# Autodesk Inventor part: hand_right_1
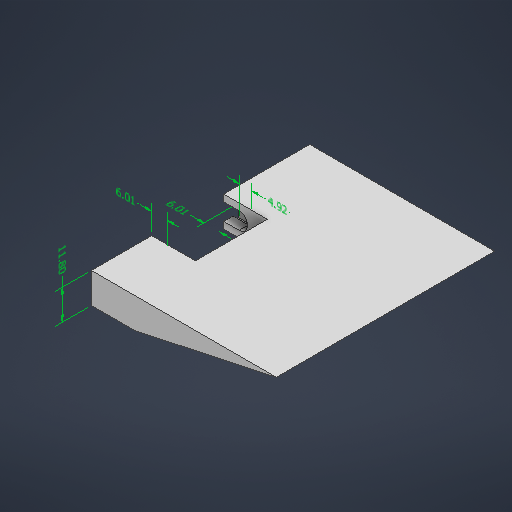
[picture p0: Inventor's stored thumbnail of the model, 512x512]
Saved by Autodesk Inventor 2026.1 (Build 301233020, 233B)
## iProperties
Created: 2025-10
Part Number: hand_right_1
Material: Generic
Document SubType Name: Modeling
Designer: Asus
Density: 1 g/cm^3
Appearance: Default
Author: Asus
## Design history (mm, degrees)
node "Annotations"
  node "Linear Dimension 2" dims "d2" = 28, "d19" = 6.01 (derived), "d25" = 8.5, "d26" = 60, "d27" = 12.02, "d28" = 72.02 (derived)
  node "Linear Dimension 3" dims "d2" = 28, "d20" = 6.01 (derived), "d25" = 8.5, "d26" = 60, "d27" = 12.02, "d28" = 72.02 (derived)
  node "Linear Dimension 4" dims "d2" = 28, "d23" = 4.915 (derived), "d25" = 8.5, "d26" = 60, "d27" = 12.02, "d28" = 72.02 (derived)
  node "Linear Dimension 5" dims "d2" = 28, "d25" = 8.5, "d26" = 60, "d27" = 12.02, "d28" = 72.02 (derived), "d31" = 11.8 (derived)
sketch "Sketch1"
  geometry: L1 (0, 0)-(60, 0); L2 (55.02, -23.5)-(55.02, -51.5); L3 (60, -75)-(0, -75); L4 (0, -75)-(0, 0); L5 (55.02, -23.5)-(72.02, -23.5); L6 (72.02, -23.5)-(72.02, -51.5); L7 (72.02, -51.5)-(55.02, -51.5); L8 (55.02, -51.5)-(55.02, -23.5); L9 (72.02, -51.5)-(55.02, -51.5); L10 (60, -75)-(72.02, -75); L11 (72.02, -75)-(72.02, -51.5); L12 (72.02, -23.5)-(55.02, -23.5); L13 (60, 0)-(72.02, 0); L14 (72.02, 0)-(72.02, -23.5); 3 further points
  constraints: 28 end point, 6 parallel, 4 horizontal, 4 midpoint, 2 perpendicular
  dimensions: "d2" = 28 distance of L5.end L6.end; "d25" = 8.5 distance of L2.end point (63.52, -51.5); "d26" = 60 distance of L3.start L3.end; "d27" = 12.02 distance of L3.start L10.end; "d28" = 72.02 distance between parallel lines of L4 L11 (derived)
extrude "Extrusion1" new body sketch "Sketch1" distance "d4" = 11.8; taper "d5" = 0 deg
sketch "Sketch2"
  geometry: L1 (17, 0)-(17, 11.8) reference; C1 r 2 at (10.99, 5.9); 1 further point
  constraints: 1 centre point
  dimensions: "d6" = 4 diameter of C1; "d7" = 6.01 distance from line of L1 C1.centre
extrude "Extrusion2" cut sketch "Sketch2" distance "d8" = 2; taper "d9" = 0 deg
sketch "Sketch3"
  geometry: L1 (6.01, 9.189)-(0, 9.189); L2 (0, 0)-(0, 11.8) reference; L3 (6.01, 2.589)-(0, 2.589); A1 r 3.3 centre (6.01, 5.889) between (6.01, 2.589) and (6.01, 9.189); 1 further point
  constraints: 4 end point, 2 point on circle, 2 point on line, 1 centre point, 1 horizontal, 1 parallel, 1 tangent
  dimensions: "d10" = 6.6 diameter of A1; "d21" = 6.01 distance from line of L2 A1.centre; "d22" = 6.01 distance of L1.start L1.end
extrude "Extrusion3" cut sketch "Sketch3" distance "d11" = 3.65; taper "d12" = 0 deg
sketch "Sketch4"
  geometry: L1 (19.85, 10.764)-(17.75, 10.764); L2 (17.75, 10.764)-(17.75, 1.014); L3 (17.75, 1.014)-(19.85, 1.014); L4 (19.85, 1.014)-(19.85, 10.764); L5 (19.85, 2.589)-(19.85, 9.189) reference; 2 further points
  constraints: 8 end point, 2 midpoint, 2 parallel, 1 horizontal, 1 perpendicular
  dimensions: "d13" = 2.1 distance of L3.end L2.end; "d14" = 9.75 distance of L1.end L2.end
extrude "Extrusion4" cut sketch "Sketch4" distance "d15" = 10.925; taper "d16" = 0 deg
sketch "Sketch5"
  geometry: L1 (17, 0)-(17, 11.8) reference; L2 (72.02, 11.8)-(0, 11.8) reference; L3 (17, 0)-(72.02, 11.8); L4 (72.02, 11.8)-(72.02, 0); L5 (72.02, 0)-(17, 0)
  constraints: 6 end point, 2 perpendicular
extrude "Extrusion5" cut sketch "Sketch5" distance "d32" = 88.5; taper "d33" = 0 deg
sketch "Sketch6"
  geometry: L1 (-72.02, 11.8)-(-17, 0) reference; L2 (0, 11.8)-(-72.02, 11.8) reference; L3 (-72.02, 11.8)-(0, 11.8); L4 (0, 11.8)-(0, 0); L5 (-17, 0)-(-17, 11.8) reference; L6 (0, 0)-(-17, 0); L7 (-17, 0)-(-72.02, 11.8); 1 further point
  constraints: 8 end point, 2 perpendicular, 1 collinear
extrude "Extrusion6" join sketch "Sketch6" distance "d34" = 10; taper "d35" = 0 deg
body "Solid1"
other parameters: "d18" = 3.20108 (derived), "d29" = 0 (derived)
